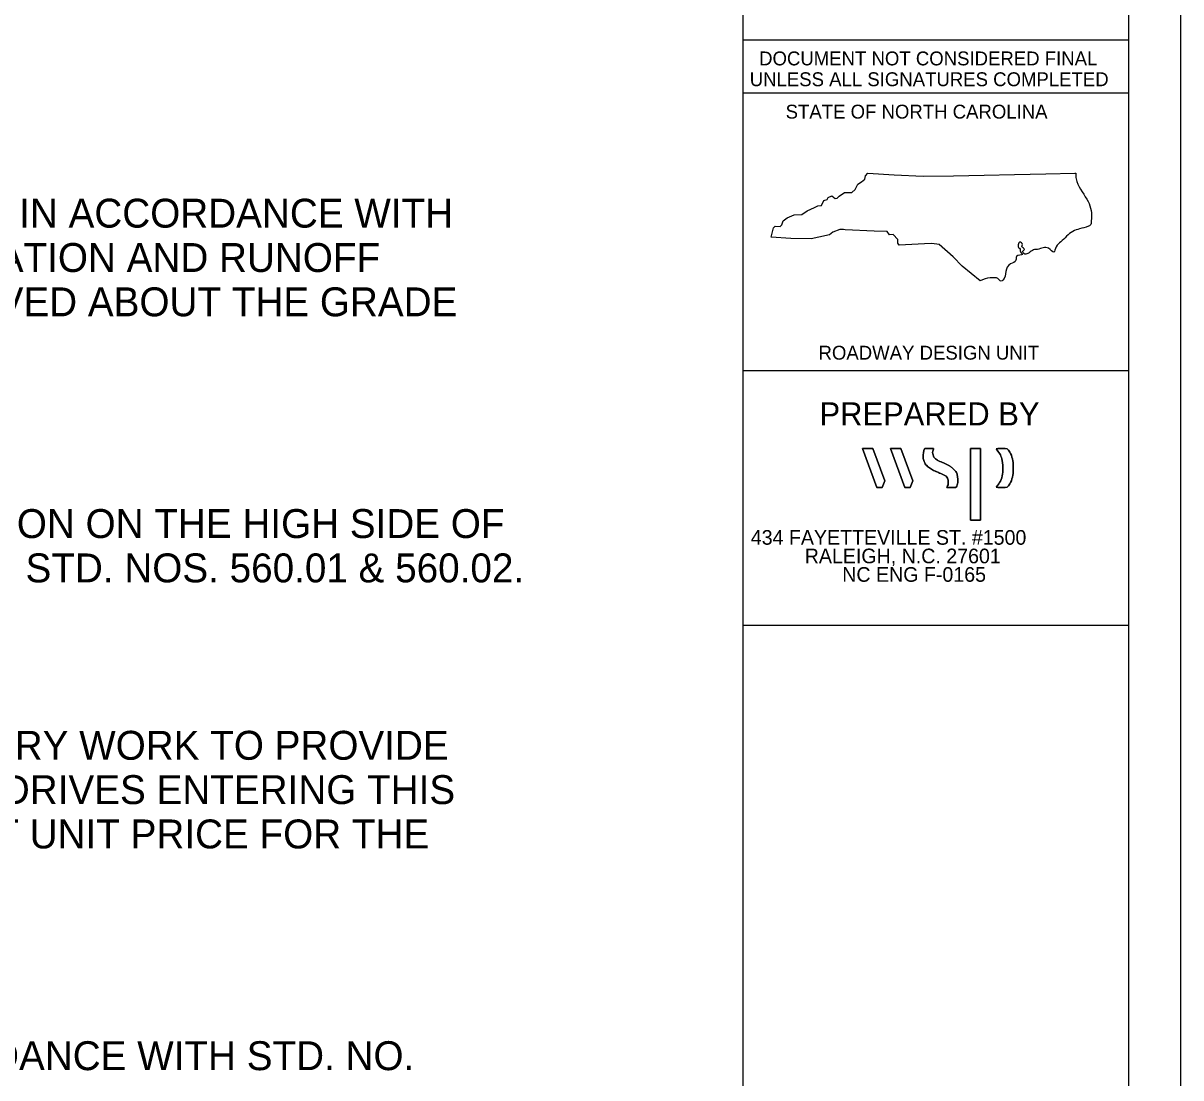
# Model space of a CAD drawing. Extents: x 1552903 to 1553045, y 811348 to 811440.
# Drawn here: x 1553019.79 to 1553044.82, y 811393.53 to 811416.33 of the extents above; entities that cross this region are included whole.
import ezdxf

# ---------------------------------------------------------------- set-up
doc = ezdxf.new("R2010")
doc.units = 0
for name, color, linetype in [('Old_Level_1', 7, 'Continuous'), ('Prop Terminator CELL', 7, 'Continuous'), ('Sheet Data Field CELL', 7, 'Continuous'), ('Sheet Plan CELL', 7, 'Continuous'), ('Sheet Sticker Incomplete CELL', 7, 'Continuous'), ('Typical Terminator CELL', 7, 'Continuous'), ('z - Construction', 7, 'Continuous')]:
    doc.layers.add(name, color=color, linetype=linetype)

msp = doc.modelspace()

# ---------------------------------------------------------------- linework, layer by layer
at = {"layer": 'Prop Terminator CELL'}
msp.add_line((1553043.689, 811350.208), (1553043.691, 811438.123), dxfattribs=at)
at = {"layer": 'Sheet Data Field CELL'}
for p, q in [((1553038.244, 811406.294), (1553037.935, 811407.133)), ((1553037.935, 811407.133), (1553038.16, 811407.133)), ((1553038.16, 811407.133), (1553038.416, 811406.437)), ((1553038.848, 811406.294), (1553038.539, 811407.133)), ((1553038.539, 811407.133), (1553038.764, 811407.133)), ((1553038.764, 811407.133), (1553039.021, 811406.437)), ((1553040.27, 811405.583), (1553040.27, 811407.133)), ((1553040.27, 811407.133), (1553040.485, 811407.133)), ((1553040.485, 811407.133), (1553040.485, 811405.583)), ((1553038.416, 811406.437), (1553038.363, 811406.294)), ((1553039.021, 811406.437), (1553038.968, 811406.294)), ((1553038.363, 811406.294), (1553038.244, 811406.294)), ((1553038.968, 811406.294), (1553038.848, 811406.294)), ((1553040.485, 811405.583), (1553040.27, 811405.583))]:
    msp.add_line(p, q, dxfattribs=at)
for points in [[(1553038.16, 811407.133), (1553037.935, 811407.133), (1553038.244, 811406.294), (1553038.363, 811406.294), (1553038.416, 811406.437), (1553038.16, 811407.133)], [(1553038.764, 811407.133), (1553038.539, 811407.133), (1553038.848, 811406.294), (1553038.968, 811406.294), (1553039.021, 811406.437), (1553038.764, 811407.133)], [(1553040.485, 811405.583), (1553040.485, 811407.133), (1553040.27, 811407.133), (1553040.27, 811405.583), (1553040.485, 811405.583)]]:
    msp.add_lwpolyline(points, dxfattribs=at)
for points in [[(1553039.249, 811407.008), (1553039.253, 811407.051), (1553039.261, 811407.094), (1553039.278, 811407.133), (1553039.278, 811407.133), (1553039.476, 811407.133), (1553039.476, 811407.133), (1553039.459, 811407.103), (1553039.444, 811407.049), (1553039.461, 811406.995), (1553039.477, 811406.946), (1553039.511, 811406.913), (1553039.553, 811406.886), (1553039.604, 811406.853), (1553039.662, 811406.835), (1553039.716, 811406.81), (1553039.773, 811406.784), (1553039.828, 811406.756), (1553039.875, 811406.715), (1553039.944, 811406.655), (1553039.986, 811406.585), (1553039.993, 811406.493), (1553039.993, 811406.482), (1553039.994, 811406.471), (1553039.994, 811406.46), (1553039.994, 811406.403), (1553039.985, 811406.346), (1553039.959, 811406.294), (1553039.959, 811406.294), (1553039.757, 811406.294), (1553039.757, 811406.294), (1553039.777, 811406.328), (1553039.792, 811406.374), (1553039.789, 811406.417), (1553039.782, 811406.523), (1553039.653, 811406.58), (1553039.545, 811406.628), (1553039.529, 811406.636), (1553039.513, 811406.643), (1553039.497, 811406.65), (1553039.45, 811406.672), (1553039.403, 811406.698), (1553039.363, 811406.732), (1553039.321, 811406.766), (1553039.289, 811406.801), (1553039.269, 811406.852), (1553039.252, 811406.897), (1553039.246, 811406.946), (1553039.248, 811406.993), (1553039.249, 811406.998), (1553039.249, 811407.003), (1553039.249, 811407.008)], [(1553039.249, 811407.008), (1553039.249, 811407.003), (1553039.249, 811406.998), (1553039.248, 811406.993), (1553039.246, 811406.946), (1553039.252, 811406.897), (1553039.269, 811406.852), (1553039.289, 811406.801), (1553039.321, 811406.766), (1553039.363, 811406.732), (1553039.403, 811406.698), (1553039.45, 811406.672), (1553039.497, 811406.65), (1553039.513, 811406.643), (1553039.529, 811406.636), (1553039.545, 811406.628), (1553039.653, 811406.58), (1553039.782, 811406.523), (1553039.789, 811406.417), (1553039.792, 811406.374), (1553039.777, 811406.328), (1553039.757, 811406.294), (1553039.757, 811406.294), (1553039.959, 811406.294), (1553039.959, 811406.294), (1553039.985, 811406.346), (1553039.994, 811406.403), (1553039.994, 811406.46), (1553039.994, 811406.471), (1553039.993, 811406.482), (1553039.993, 811406.493), (1553039.986, 811406.585), (1553039.944, 811406.655), (1553039.875, 811406.715), (1553039.828, 811406.756), (1553039.773, 811406.784), (1553039.716, 811406.81), (1553039.662, 811406.835), (1553039.604, 811406.853), (1553039.553, 811406.886), (1553039.511, 811406.913), (1553039.477, 811406.946), (1553039.461, 811406.995), (1553039.444, 811407.049), (1553039.459, 811407.103), (1553039.476, 811407.133), (1553039.476, 811407.133), (1553039.278, 811407.133), (1553039.278, 811407.133), (1553039.261, 811407.094), (1553039.253, 811407.051), (1553039.249, 811407.008)], [(1553040.967, 811406.714), (1553040.967, 811406.89), (1553040.903, 811407.037), (1553040.819, 811407.133), (1553040.819, 811407.133), (1553041.063, 811407.133), (1553041.063, 811407.133), (1553041.143, 811407.035), (1553041.193, 811406.869), (1553041.193, 811406.714), (1553041.193, 811406.714), (1553041.193, 811406.713), (1553041.193, 811406.713), (1553041.193, 811406.558), (1553041.143, 811406.392), (1553041.063, 811406.294), (1553041.063, 811406.294), (1553040.818, 811406.294), (1553040.818, 811406.294), (1553040.902, 811406.39), (1553040.967, 811406.537), (1553040.967, 811406.713), (1553040.967, 811406.713), (1553040.967, 811406.714), (1553040.967, 811406.714)], [(1553040.967, 811406.714), (1553040.967, 811406.714), (1553040.967, 811406.713), (1553040.967, 811406.713), (1553040.967, 811406.537), (1553040.902, 811406.39), (1553040.818, 811406.294), (1553040.818, 811406.294), (1553041.063, 811406.294), (1553041.063, 811406.294), (1553041.143, 811406.392), (1553041.193, 811406.558), (1553041.193, 811406.713), (1553041.193, 811406.713), (1553041.193, 811406.714), (1553041.193, 811406.714), (1553041.193, 811406.869), (1553041.143, 811407.035), (1553041.063, 811407.133), (1553041.063, 811407.133), (1553040.819, 811407.133), (1553040.819, 811407.133), (1553040.903, 811407.037), (1553040.967, 811406.89), (1553040.967, 811406.714)]]:
    msp.add_open_spline(points, degree=3, dxfattribs=at)
at = {"layer": 'Sheet Sticker Incomplete CELL'}
msp.add_line((1553042.544, 811413.084), (1553042.544, 811413.088), dxfattribs=at)
for points in [[(1553035.961, 811411.7), (1553036.013, 811411.906), (1553036.046, 811411.943), (1553036.157, 811411.936), (1553036.194, 811411.972), (1553036.224, 811412.053), (1553036.307, 811412.117), (1553036.462, 811412.188), (1553036.626, 811412.19), (1553036.741, 811412.271), (1553036.896, 811412.34), (1553036.973, 811412.381), (1553037.048, 811412.383), (1553037.098, 811412.496), (1553037.172, 811412.517), (1553037.196, 811412.557), (1553037.275, 811412.594), (1553037.347, 811412.541), (1553037.386, 811412.545), (1553037.43, 811412.586), (1553037.546, 811412.669), (1553037.705, 811412.671), (1553037.776, 811412.732), (1553037.838, 811412.846), (1553037.915, 811412.9), (1553037.987, 811412.955), (1553038.003, 811413.031), (1553038.049, 811413.088)], [(1553038.049, 811413.088), (1553038.619, 811413.047), (1553039.248, 811413.022), (1553039.901, 811413.031), (1553040.567, 811413.042), (1553041.222, 811413.053), (1553041.899, 811413.074), (1553042.526, 811413.088), (1553042.544, 811413.088)], [(1553040.478, 811410.758), (1553040.092, 811411.075), (1553039.895, 811411.279), (1553039.593, 811411.541), (1553039.437, 811411.565), (1553039.272, 811411.557), (1553038.731, 811411.531), (1553038.7, 811411.57), (1553038.7, 811411.61), (1553038.697, 811411.65), (1553038.598, 811411.76), (1553038.521, 811411.75), (1553038.468, 811411.824), (1553038.191, 811411.832), (1553037.563, 811411.86), (1553037.524, 811411.867), (1553037.449, 811411.868), (1553037.294, 811411.813), (1553037.219, 811411.753), (1553036.989, 811411.705), (1553036.826, 811411.668), (1553036.388, 811411.673), (1553035.961, 811411.7)]]:
    msp.add_lwpolyline(points, dxfattribs=at)
for points in [[(1553042.544, 811413.084), (1553042.554, 811412.962), (1553042.784, 811412.523), (1553042.867, 811412.328), (1553042.885, 811412.128), (1553042.875, 811411.999)], [(1553042.625, 811411.883), (1553042.482, 811411.827), (1553042.221, 811411.602), (1553042.12, 811411.49), (1553042.069, 811411.376), (1553041.957, 811411.461), (1553041.719, 811411.439), (1553041.632, 811411.427), (1553041.441, 811411.337), (1553041.405, 811411.365), (1553041.403, 811411.401), (1553041.435, 811411.438), (1553041.38, 811411.506), (1553041.393, 811411.542), (1553041.33, 811411.595), (1553041.308, 811411.557), (1553041.309, 811411.48), (1553041.345, 811411.445), (1553041.343, 811411.407), (1553041.391, 811411.331), (1553041.265, 811411.285), (1553041.251, 811411.203), (1553041.135, 811411.125), (1553041.032, 811410.961), (1553040.97, 811410.77), (1553040.933, 811410.752), (1553040.859, 811410.811), (1553040.733, 811410.821), (1553040.696, 811410.821), (1553040.478, 811410.758)], [(1553042.875, 811411.999), (1553042.856, 811411.958), (1553042.82, 811411.937), (1553042.625, 811411.883)]]:
    msp.add_spline(points, degree=3, dxfattribs=at)
at = {"layer": 'Typical Terminator CELL'}
msp.add_line((1553044.816, 811348.333), (1553044.816, 811439.998), dxfattribs=at)
at = {"layer": 'z - Construction'}
for p, q in [((1553035.356, 811350.208), (1553035.358, 811438.123)), ((1553043.691, 811415.963), (1553035.358, 811415.963)), ((1553043.691, 811414.813), (1553035.358, 811414.813)), ((1553043.691, 811408.813), (1553035.358, 811408.813)), ((1553043.691, 811403.313), (1553035.358, 811403.313))]:
    msp.add_line(p, q, dxfattribs=at)

# ---------------------------------------------------------------- texts
at = {"layer": 'Old_Level_1'}
for s, p in [('434 FAYETTEVILLE ST. #1500', (1553035.521, 811405.055)), ('RALEIGH, N.C. 27601', (1553036.687, 811404.654)), ('NC ENG F-0165', (1553037.498, 811404.254))]:
    msp.add_text(s, height=0.31671, rotation=360, dxfattribs=at).set_placement(p)
at = {"layer": 'Sheet Data Field CELL'}
for s, height, p in [('DOCUMENT NOT CONSIDERED FINAL', 0.3, (1553035.701, 811415.415)), ('UNLESS ALL SIGNATURES COMPLETED', 0.3, (1553035.498, 811414.965)), ('STATE OF NORTH CAROLINA', 0.3, (1553036.274, 811414.265)), ('ROADWAY DESIGN UNIT', 0.3, (1553036.985, 811409.055)), ('PREPARED BY', 0.5, (1553037.006, 811407.633))]:
    msp.add_text(s, height=height, dxfattribs=at).set_placement(p)
at = {"layer": 'Sheet Plan CELL'}
for s, p in [('         ALL CURVES ON THIS PROJECT SHALL BE SUPERELEVATED IN ACCORDANCE WITH', (1552992.723, 811411.908)), ('         STD. NOS. 225.04 & 225.05 USING THE RATE OF SUPERELEVATION AND RUNOFF ', (1552992.723, 811410.95)), ('         SHOWN ON THE PLANS. SUPERELEVATION IS TO BE REVOLVED ABOUT THE GRADE ', (1552992.723, 811409.992)), ('         ASPHALT, EARTH, AND CONCRETE SHOULDER CONSTRUCTION ON THE HIGH SIDE OF', (1552992.723, 811405.2)), ('         SUPERELEVATED CURVES SHALL BE IN ACCORDANCE WITH STD. NOS. 560.01 & 560.02.', (1552992.723, 811404.242)), ('         THE CONTRACTOR WILL BE REQUIRED TO DO ALL NECESSARY WORK TO PROVIDE ', (1552992.723, 811400.408)), ('         SUITABLE CONNECTIONS WITH ALL ROADS, STREETS, AND DRIVES ENTERING THIS ', (1552992.723, 811399.45)), ('         PROJECT. THIS WORK WILL BE PAID FOR AT THE CONTRACT UNIT PRICE FOR THE ', (1552992.723, 811398.492)), ('         SUBSURFACE DRAINS SHALL BE CONSTRUCTED IN ACCORDANCE WITH STD. NO. ', (1552992.723, 811393.7))]:
    msp.add_text(s, height=0.625, dxfattribs=at).set_placement(p)

doc.saveas('drawing.dxf')
